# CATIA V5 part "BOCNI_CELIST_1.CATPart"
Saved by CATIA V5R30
Part number: BOCNI_CELIST_1
Bounding box of the stored display mesh (mm): x 41.822 to 99.822, y -31.5 to 31.5, z -23.056 to -3.056
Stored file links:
  C:\Users\ondra\Desktop\PŘÍLOHA P III\CATIA\BOCNI_CELIST_1.CATPart
  C:\Users\ondra\Desktop\FORMA_BAKALARKA\Part1.CATPart
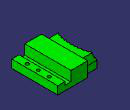
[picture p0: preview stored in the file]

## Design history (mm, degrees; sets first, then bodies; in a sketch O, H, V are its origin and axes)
Body1 (main body)
  Body2 "BOCNI TVARNIK 1"
    Solid1: linked copy from another document
  Assemble1: tool Body2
